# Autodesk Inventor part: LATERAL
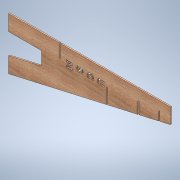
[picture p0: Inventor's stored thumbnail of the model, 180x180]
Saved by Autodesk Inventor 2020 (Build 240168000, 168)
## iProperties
Part Number: LATERAL
Material: Madera (abedul)
Document SubType Name: Modeling
Designer: Arias
Mass: 0.170564 g
Surface Area: 12.6786 cm^2
Volume: 0.110684 cm^3
Density: 0.55 g/cm^3
Appearance: Abedul - Natural pulido
Author: Arias
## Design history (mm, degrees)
sketch "Boceto4"
  geometry: L1 (0, 0)-(-2440, 0); L2 (-2440, 0)-(-2440, -1220); L3 (-2440, -1220)-(0, -1220); L4 (0, -1220)-(0, 0); L5 (-42.072, -54.378)-(-42.072, -204.378); L6 (-42.072, -204.378)-(-357.424, -204.378); L7 (-42.072, -554.378)-(-42.072, -404.378); L8 (-1592.072, -54.378)-(-1592.072, -201.619); L9 (-42.072, -404.378)-(-357.424, -332.608); L10 (-1492.072, -139.378)-(-1492.072, -224.378); L11 (-1292.072, -162.136)-(-1292.072, -269.895); L12 (-992.072, -196.274)-(-992.072, -338.171); L13 (-357.424, -204.378)-(-357.424, -332.608); L14 (-542.072, -54.378)-(-542.072, -176.378); L15 (-1480.972, -226.904)-(-1480.972, -139.378); L16 (-1492.072, -139.378)-(-1480.972, -139.378); L17 (-1280.972, -272.421)-(-1280.972, -162.136); L18 (-980.972, -340.697)-(-980.972, -196.274); L19 (-1292.072, -162.136)-(-1280.972, -162.136); L20 (-992.072, -196.274)-(-980.972, -196.274); L21 (-530.972, -54.378)-(-530.972, -176.378); L22 (-542.072, -176.378)-(-530.972, -176.378); L23 (-980.972, -340.697)-(-42.072, -554.378); L24 (-1280.972, -272.421)-(-992.072, -338.171); L25 (-1592.072, -201.619)-(-1492.072, -224.378); L26 (-1480.972, -226.904)-(-1292.072, -269.895); L27 (-42.072, -54.378)-(-530.972, -54.378); L28 (-542.072, -54.378)-(-1592.072, -54.378)
  constraints: 56 end point, 8 vertical, 7 parallel, 6 horizontal, 3 perpendicular
  dimensions: "d11" = 2440 distance of L3.end L2.end; "d12" = 1220 distance of L2.end L1.end; "d14" = 1550 distance of L5.start L8.start; "d15" = 150 distance of L5.start L5.end; "d17" = 500 distance of L5.start L7.start; "d18" = 150 distance of L7.start L7.end; "d22" = 100 distance from line of L8 L10.start; "d26" = 11.1 distance between parallel lines of L15 L10; "d27" = 11.1 distance between parallel lines of L11 L17; "d28" = 11.1 distance between parallel lines of L12 L18; "d29" = 11.1 distance between parallel lines of L21 L14; "d33" = 122 distance of L14.start L14.end
extrude "Extrusión2" new body sketch "Boceto4" distance "d31" = 11.1; taper "d32" = 0 deg
sketch "Boceto5"
  geometry: L1 (956.836, -154.24)-(956.836, -517.396); L2 (956.836, -517.396)-(742.833, -517.396); L3 (742.833, -517.396)-(742.833, -154.24); L4 (742.833, -154.24)-(956.836, -154.24); 1 further point
  constraints: 2 other
extrude "Extrusión3" cut sketch "Boceto5" distance "d34" = 12; taper "d35" = 0 deg
node "Sólido2"
other parameters: "sa_0" = 140000, "sa_1" = 0, "sa_2" = 0, "sa_3" = -2000000, "d21" = 90 deg, "d30" = 245
